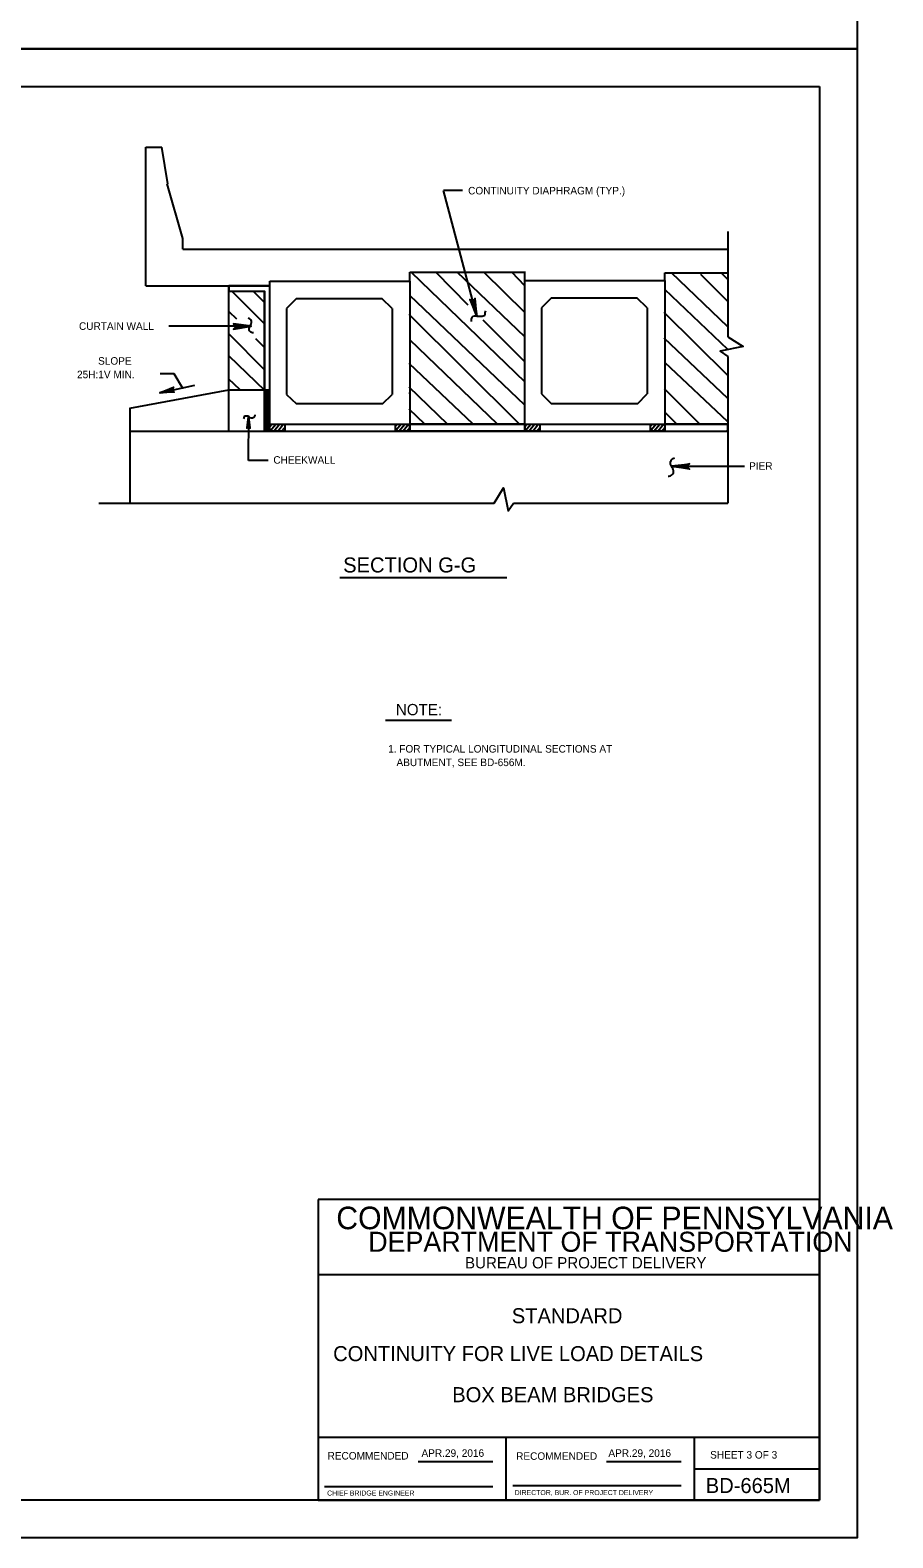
# Model space of a CAD drawing. Extents: x 641517 to 642372, y 298537 to 300319.
# Drawn here: x 642028 to 642372, y 298537 to 299138 of the extents above; entities that cross this region are included whole.
import ezdxf

# ---------------------------------------------------------------- set-up
doc = ezdxf.new("R2010")
doc.units = 0
doc.layers.add('2', color=7, linetype='Continuous')
doc.layers.add('PLT-BNDY', color=7, linetype='Continuous')

msp = doc.modelspace()

# ---------------------------------------------------------------- linework, layer by layer
at = {"layer": '2'}
for p, q in [((641557.05, 299115.62), (642343.05, 299115.62)), ((642343.05, 299115.62), (642343.05, 298551.62)), ((642074.38, 299036.08), (642074.38, 299091.43)), ((642074.38, 299091.43), (642080.77, 299091.43)), ((642074.38, 299036.08), (642074.38, 299091.43)), ((642083.14, 299076.76), (642080.77, 299091.43)), ((642089.05, 299055), (642082.9, 299076.76)), ((642206.37, 299024.02), (642193.12, 299074.16)), ((642200.69, 299074.16), (642193.12, 299074.16)), ((642089.05, 299050.74), (642089.05, 299055.24)), ((642306.42, 299057.84), (642306.42, 299015.74)), ((642089.05, 299050.74), (642306.42, 299050.74)), ((642225.53, 299038.21), (642225.53, 299041.76)), ((642074.38, 299036.08), (642107.5, 299036.08)), ((642107.5, 299036.08), (642123.82, 299036.08)), ((642107.5, 298978.13), (642107.5, 299036.08)), ((642123.82, 299037.97), (642179.64, 299037.97)), ((642123.82, 298978.13), (642123.82, 299037.97)), ((642179.64, 299037.97), (642179.64, 299041.52)), ((642179.64, 299041.52), (642225.76, 299041.52)), ((642179.64, 299037.97), (642179.64, 298978.13)), ((642180.11, 299041.52), (642225.53, 298997.76)), ((642190.05, 299041.52), (642202.82, 299028.51)), ((642225.53, 299015.74), (642198.56, 299041.52)), ((642225.53, 299025.44), (642209.21, 299041.52)), ((642225.53, 299036.08), (642220.32, 299041.52)), ((642225.53, 299038.21), (642281.35, 299038.21)), ((642225.53, 298978.13), (642225.53, 299038.21)), ((642281.35, 299037.97), (642281.35, 299041.28)), ((642281.35, 299041.28), (642306.42, 299041.28)), ((642281.35, 299038.21), (642281.35, 298978.13)), ((642306.42, 299019.76), (642283.95, 299041.28)), ((642295.54, 299040.81), (642306.18, 299030.17)), ((642303.82, 299041.28), (642306.42, 299038.68)), ((642107.5, 299033.95), (642121.69, 299033.95)), ((642108.68, 299033.95), (642121.7, 299020.94)), ((642117.2, 299033.95), (642121.72, 299029.43)), ((642121.69, 298978.13), (642121.69, 299033.95)), ((642134.46, 299031.11), (642130.44, 299027.09)), ((642134.46, 299031.11), (642168.52, 299031.11)), ((642172.54, 299027.09), (642168.52, 299031.11)), ((642225.53, 298988.54), (642179.64, 299032.3)), ((642236.17, 299031.35), (642232.15, 299027.33)), ((642236.17, 299031.35), (642270.23, 299031.35)), ((642274.25, 299027.33), (642270.23, 299031.35)), ((642306.42, 299010.77), (642281.35, 299034.66)), ((642107.5, 299025.91), (642110.45, 299022.91)), ((642130.44, 299027.09), (642130.44, 298992.79)), ((642172.54, 299027.09), (642172.54, 298992.79)), ((642223.4, 298980.97), (642179.4, 299024.73)), ((642232.15, 299027.33), (642232.15, 298993.03)), ((642274.25, 299027.33), (642274.25, 298993.03)), ((642306.42, 299000.36), (642281.11, 299025.44)), ((642116.41, 299020), (642083.53, 299020)), ((642208.73, 299022.6), (642225.53, 299005.8)), ((642107.5, 299016.92), (642121.63, 299002.56)), ((642118.12, 299015.11), (642121.74, 299011.44)), ((642214.65, 298980.97), (642179.64, 299014.56)), ((642306.42, 298991.14), (642281.11, 299015.27)), ((642107.5, 299008.17), (642121.7, 298994.43)), ((642306.42, 299007.93), (642306.42, 298949.39)), ((642085.59, 299000.99), (642079.99, 299000.99)), ((642088.9, 298995.47), (642085.59, 299000.99)), ((642204.95, 298980.97), (642179.4, 299005.09)), ((642306.42, 298981.91), (642281.35, 299005.57)), ((642067.9, 298987.26), (642107.5, 298994.69)), ((642079.95, 298993.49), (642093.84, 298996.49)), ((642111.87, 298994.78), (642107.5, 298998.94)), ((642107.5, 298994.69), (642121.69, 298994.69)), ((642121.69, 298994.69), (642123.82, 298994.69)), ((642122.16, 298978.13), (642122.16, 298994.69)), ((642122.64, 298978.13), (642122.64, 298994.69)), ((642122.87, 298978.13), (642122.87, 298994.69)), ((642123.35, 298978.13), (642123.35, 298994.69)), ((642194.71, 298980.93), (642179.4, 298995.63)), ((642281.11, 298995.16), (642295.3, 298980.97)), ((642130.44, 298992.79), (642134.46, 298989.01)), ((642168.76, 298989.01), (642134.46, 298989.01)), ((642168.76, 298989.01), (642172.54, 298992.79)), ((642179.64, 298993.03), (642179.64, 298993.5)), ((642232.15, 298993.03), (642236.17, 298989.01)), ((642270.47, 298989.01), (642236.17, 298989.01)), ((642270.47, 298989.01), (642274.25, 298993.03)), ((642067.9, 298987.26), (642067.9, 298949.39)), ((642115.3, 298966.48), (642115.41, 298983.95)), ((642123.82, 298978.13), (642123.82, 298983.08)), ((642185.55, 298980.97), (642179.4, 298986.88)), ((642281.35, 298985.7), (642286.08, 298980.97)), ((642067.9, 298978.13), (642306.42, 298978.13)), ((642123.81, 298978.13), (642126.12, 298980.93)), ((642123.82, 298980.97), (642179.64, 298980.97)), ((642123.82, 298980.03), (642124.59, 298980.97)), ((642129.73, 298978.13), (642123.82, 298978.13)), ((642125.38, 298978.13), (642127.71, 298980.95)), ((642126.96, 298978.16), (642129.3, 298981)), ((642128.51, 298978.13), (642129.73, 298979.61)), ((642129.73, 298980.97), (642129.73, 298978.13)), ((642173.72, 298978.13), (642176.03, 298980.93)), ((642173.73, 298980.97), (642173.73, 298978.13)), ((642173.73, 298980.03), (642174.5, 298980.97)), ((642179.64, 298978.13), (642173.73, 298978.13)), ((642175.29, 298978.13), (642177.62, 298980.95)), ((642176.87, 298978.16), (642179.21, 298981)), ((642178.42, 298978.13), (642179.64, 298979.61)), ((642179.64, 298980.97), (642225.53, 298980.97)), ((642225.52, 298978.13), (642227.83, 298980.93)), ((642225.53, 298980.97), (642281.35, 298980.97)), ((642225.53, 298980.03), (642226.3, 298980.97)), ((642231.44, 298978.13), (642225.53, 298978.13)), ((642227.09, 298978.13), (642229.42, 298980.95)), ((642228.67, 298978.16), (642231.01, 298981)), ((642230.22, 298978.13), (642231.44, 298979.61)), ((642231.44, 298980.97), (642231.44, 298978.13)), ((642275.43, 298978.13), (642277.74, 298980.93)), ((642275.44, 298980.97), (642275.44, 298978.13)), ((642275.44, 298980.03), (642276.21, 298980.97)), ((642281.35, 298978.13), (642275.44, 298978.13)), ((642276.99, 298978.13), (642279.32, 298980.95)), ((642278.58, 298978.16), (642280.92, 298981)), ((642280.13, 298978.13), (642281.35, 298979.61)), ((642281.35, 298980.97), (642306.42, 298980.97)), ((642305.91, 298978.13), (642306.42, 298978.64)), ((642123.13, 298966.48), (642115.3, 298966.48)), ((642284.03, 298964.15), (642313.08, 298964.15)), ((642055.59, 298949.39), (642213.24, 298949.39)), ((642221.04, 298949.39), (642306.42, 298949.39)), ((642218.33, 298919.63), (642151.71, 298919.63)), ((642169.94, 298862.78), (642196.19, 298862.78)), ((642343.05, 298671.62), (642143.05, 298671.62)), ((642143.05, 298671.62), (642143.05, 298551.62)), ((642343.05, 298551.62), (642343.05, 298671.62)), ((642343.05, 298641.62), (642143.05, 298641.62)), ((642343.05, 298641.62), (642143.05, 298641.62)), ((642343.05, 298576.62), (642143.05, 298576.62)), ((642218.05, 298551.62), (642218.05, 298576.62)), ((642293.05, 298576.62), (642293.05, 298551.62)), ((642183.01, 298567.12), (642212.78, 298567.12)), ((642258.01, 298567.12), (642287.92, 298567.12)), ((642293.05, 298564.12), (642343.05, 298564.12)), ((642145.55, 298557.12), (642212.78, 298557.12)), ((642220.67, 298557.5), (642287.92, 298557.5)), ((642343.05, 298551.62), (641557.05, 298551.62)), ((642143.05, 298551.62), (642343.05, 298551.62))]:
    msp.add_line(p, q, dxfattribs=at)
for points in [[(642107.5, 299036.08), (642107.5, 299033.95), (642121.69, 299033.95), (642121.69, 298994.69), (642123.82, 298994.69), (642123.82, 299036.08)], [(642179.64, 298980.97), (642225.53, 298980.97), (642225.53, 298978.13), (642179.64, 298978.13)], [(642179.64, 298980.97), (642179.64, 298978.13), (642225.53, 298978.13), (642225.53, 298980.97)], [(642281.35, 298980.97), (642281.35, 298978.13), (642306.42, 298978.13), (642306.42, 298980.97)]]:
    msp.add_lwpolyline(points, close=True, dxfattribs=at)
for points in [[(642203.77, 299030.4), (642204.24, 299030.17), (642206.37, 299024.02), (642203.77, 299030.4), (642203.53, 299030.64), (642206.37, 299024.02), (642204.95, 299030.4), (642205.42, 299030.64), (642206.37, 299024.02), (642205.66, 299031.11), (642205.42, 299030.64)], [(642109.55, 299019.06), (642110.02, 299019.53), (642116.41, 299020), (642109.55, 299019.06), (642109.31, 299018.82), (642116.41, 299020), (642110.02, 299020.24), (642109.78, 299020.71), (642116.41, 299020), (642109.31, 299020.95), (642109.78, 299020.71)], [(642306.42, 299015.74), (642312.57, 299011.95), (642303.35, 299010.06), (642306.42, 299007.93)], [(642085.35, 298993.95), (642085.11, 298994.3), (642079.95, 298993.49), (642085.35, 298993.95), (642085.62, 298993.76), (642079.95, 298993.49), (642084.89, 298994.79), (642085.11, 298995.21), (642079.95, 298993.49), (642085.33, 298995.63), (642085.11, 298995.21)], [(642115.86, 298979.45), (642115.56, 298979.6), (642115.26, 298983.8), (642115.86, 298979.45), (642116.01, 298979.3), (642115.26, 298983.8), (642115.11, 298979.6), (642114.81, 298979.45), (642115.26, 298983.8), (642114.66, 298979.3), (642114.81, 298979.45)], [(642290.89, 298963.2), (642290.41, 298963.68), (642284.03, 298964.15), (642290.89, 298963.2), (642291.12, 298962.97), (642284.03, 298964.15), (642290.41, 298964.39), (642290.65, 298964.86), (642284.03, 298964.15), (642291.12, 298965.1), (642290.65, 298964.86)], [(642213.24, 298949.39), (642217.02, 298955.54), (642218.91, 298946.32), (642221.04, 298949.39)]]:
    msp.add_lwpolyline(points, dxfattribs=at)
msp.add_circle((642088.9, 298995.47), 0.215, dxfattribs=at)
for points in [[(642204.24, 299021.89), (642204.24, 299022.83), (642204.95, 299024.02), (642206.84, 299024.02), (642207.31, 299024.02), (642208.5, 299024.02), (642209.68, 299024.73), (642209.68, 299025.44), (642209.92, 299026.15)], [(642117.27, 299017.32), (642116.51, 299017.51), (642115.56, 299018.45), (642115.75, 299019.78), (642116.13, 299020.54), (642116.51, 299021.48), (642116.13, 299022.62), (642115.94, 299022.81), (642115.19, 299023.19)], [(642117.81, 298984.7), (642117.66, 298984.1), (642116.91, 298983.35), (642115.86, 298983.5), (642115.41, 298983.95), (642114.51, 298984.1), (642113.61, 298983.95), (642113.46, 298983.65), (642113.31, 298983.05)], [(642282.61, 298960.13), (642283.55, 298960.37), (642284.74, 298961.55), (642284.5, 298963.2), (642284.03, 298964.15), (642283.55, 298965.33), (642284.03, 298966.75), (642284.26, 298966.99), (642285.21, 298967.46)]]:
    msp.add_spline(points, degree=3, dxfattribs=at)
at = {"layer": 'PLT-BNDY'}
for points in [[(641517.05, 299724.62), (642358.05, 299724.62), (642358.05, 299130.62), (641517.05, 299130.62)], [(641517.05, 299130.62), (642358.05, 299130.62), (642358.05, 298536.62), (641517.05, 298536.62)]]:
    msp.add_lwpolyline(points, close=True, dxfattribs=at)

# ---------------------------------------------------------------- texts
at = {"layer": '2'}
for s, height, p in [('CONTINUITY DIAPHRAGM (TYP.)', 3, (642202.88, 299072.59)), ('CURTAIN WALL', 3, (642047.67, 299018.56)), ('SLOPE', 3, (642055.28, 299004.66)), ('25H:1V MIN.', 3, (642046.9, 298999.26)), ('CHEEKWALL', 3, (642125.2, 298965.16)), ('PIER', 3, (642314.95, 298962.75)), ('SECTION G-G', 6, (642153.05, 298921.76)), ('NOTE:', 4.5, (642174.08, 298864.81)), ('1. FOR TYPICAL LONGITUDINAL SECTIONS AT', 3, (642170.97, 298849.91)), ('   ABUTMENT, SEE BD-656M.', 3, (642170.97, 298844.51)), ('COMMONWEALTH OF PENNSYLVANIA', 9, (642150.3, 298659.75)), ('DEPARTMENT OF TRANSPORTATION', 8.0002, (642163.05, 298650.75)), ('BUREAU OF PROJECT DELIVERY', 4.5, (642201.64, 298644.12)), ('STANDARD', 6, (642220.3, 298622.25)), ('CONTINUITY FOR LIVE LOAD DETAILS', 6, (642149.05, 298607.12)), ('BOX BEAM BRIDGES', 6, (642196.55, 298590.75)), ('APR.29, 2016', 3, (642184.29, 298568.94)), ('APR.29, 2016', 3, (642258.83, 298568.94)), ('SHEET 3 OF 3', 3, (642299.42, 298568.25)), ('BD-665M', 6, (642297.67, 298554.5)), ('CHIEF BRIDGE ENGINEER', 2.0002, (642146.64, 298553.5)), ('DIRECTOR, BUR. OF PROJECT DELIVERY', 2.0002, (642221.43, 298553.68))]:
    msp.add_text(s, height=height, dxfattribs=at).set_placement(p)
for p in [(642146.82, 298567.87), (642222.03, 298567.75)]:
    msp.add_text('RECOMMENDED', height=3, rotation=360, dxfattribs=at).set_placement(p)

doc.saveas('drawing.dxf')
